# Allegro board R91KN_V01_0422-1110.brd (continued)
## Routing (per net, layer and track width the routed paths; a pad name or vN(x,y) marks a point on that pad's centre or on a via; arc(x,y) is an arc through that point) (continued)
ODTA1: length 49.4
  TOP w0.097: v3(128.95,68.44) 128.8,68.44 128.68,68.56 128.68,68.99 128.5,69.17 128.5,70.52 128.45,70.57 128.45,71.37 128.57,71.49 128.76,71.49 128.85,71.58 128.85,71.7 128.76,71.79 128.12,71.79 128.03,71.88 128.03,72 128.12,72.09 129.91,72.09 130,72.18 130,72.76 130.09,72.84 130.21,72.84 130.3,72.76 130.3,72.18 130.39,72.09 130.51,72.09 130.6,72.18 130.6,72.76 130.69,72.84 130.81,72.84 130.9,72.76 130.9,72.18 130.99,72.09 131.63,72.09 132.12,72.58 132.56,72.58
  BOTTOM w0.097: v3(128.95,68.44) 129.23,68.16 129.23,65.51 129.38,65.36 129.38,62.95 130.51,61.81 131.72,61.81 R228.2 ; R230.2 141,61.3 141,69.4 140.91,69.49 140.58,69.49 140.49,69.58 140.49,69.7 140.58,69.79 140.91,69.79 141,69.88 141,70 140.91,70.09 140.21,70.09 140.12,70.18 140.12,70.3 140.21,70.39 140.91,70.39 141,70.48 141,70.6 140.91,70.69 140.1,70.69 140.01,70.78 140.01,70.9 140.1,70.99 140.91,70.99 141,71.08 v4(141,71.61) 141,72.05 140.88,72.17 139.09,72.17 138.97,72.3 U402.K1
  BOTTOM w0.1: R230.2 140.48,60.81 139.76,60.09 R227.1 139.54,59.89 139.13,59.89 138.41,59.16 135.94,59.16 135.81,59.29 134.68,59.29 134.45,59.52 134.45,59.53 134.14,59.84 134.14,60.07 133.26,60.95 132.64,60.95 R228.2
ODTA1_R: length 42.7
  TOP w0.1: U1.K16 v1(95.9,59.05)
  BOTTOM w0.1: v1(95.9,59.05) 96.09,59.05 96.63,59.6 96.74,59.6 97.81,60.67 98.14,60.67 98.46,60.35 98.61,60.2 99.67,60.2 99.68,60.2 99.73,60.19 100.69,59.23 101.06,59.23 101.24,59.41 101.24,59.63 101.47,59.86 101.75,59.86 101.76,59.84 101.81,59.84 102.05,59.6 102.05,59.33 102.14,59.23 102.27,59.23 102.72,58.77 106.02,58.77 106.7,58.09 130.47,58.09 130.62,57.94 131.9,57.94 132.84,58.88 133.25,58.88 133.53,59.15 133.53,60.01 R228.1
PCIE_CALRN: length 2.3
  TOP w0.25: U1.AA22 86.98,54.6 87.61,53.97 v1(87.77,53.97)
  BOTTOM w0.3: v1(87.77,53.97) 87.54,53.97 87.13,53.55 R8.2
PCIE_CALRP: length 1.4
  TOP w0.3: v1(87.27,55.04) 87.29,55.04 87.73,54.6 U1.Y22
  BOTTOM w0.3: R9.1 86.85,55.59 87.27,55.17 v1(87.27,55.04)
PCIE_REFCLKN: length 56.1
  TOP w0.1: U1.AK32 80.12,48.2 79.98,48.06 79.98,47.81 80.21,47.58 80.21,47.23 79.95,46.98 79.85,46.98 79.7,46.82 v1(79.7,46.56)
  BOTTOM w0.125: v1(79.7,46.56) 79.78,46.64 79.78,46.79 79.65,46.91 79.39,46.91 79.15,46.67 79.15,40.27 74.95,36.08 74.95,22.8 66.35,14.2 63.27,14.2 60.3,11.23 60.3,6.1 60.65,5.75 MPCIE1.A14
PCIE_REFCLKP: length 56
  TOP w0.1: v1(79.81,47.42) 79.74,47.49 79.74,48.31 80.07,48.64 80.07,48.92 U1.AK30
  BOTTOM w0.125: v1(79.81,47.42) 79.6,47.21 79.27,47.21 78.93,46.88 78.85,46.79 78.85,40.4 74.65,36.2 74.65,22.92 66.23,14.5 63.15,14.5 60,11.35 60,6.1 59.65,5.75 MPCIE1.A13
PCIE_TX0N: length 47.5
  TOP w0.1: v1(81.05,46.67) 81.05,46.76 81.21,46.91 81.22,46.91 81.45,47.15 81.45,47.16 81.45,47.57 81.48,47.6 81.48,48.43 81.65,48.6 U1.AG31
  BOTTOM w0.125: C4.1 63.3,11.54 63.3,12.12 64.08,12.9 66.77,12.9 76.15,22.28 76.15,35.6 80.5,39.95 80.5,46.8 80.59,46.9 80.95,46.9 81.05,46.8 v1(81.05,46.67)
PCIE_TX0P: length 47.5
  TOP w0.1: v1(81.05,47.31) 81.05,47.45 81.28,47.68 81.28,48.67 U1.AH30
  BOTTOM w0.125: C3.1 63,11.54 63,12.24 63.96,13.2 66.65,13.2 75.85,22.4 75.85,35.72 80.19,40.07 80.19,46.92 80.47,47.2 80.94,47.2 v1(81.05,47.31)
PCIE_TX1N: length 45.7
  TOP w0.125: v1(82.17,50.23) 82.17,50.18 U1.AF28
  BOTTOM w0.125: C6.1 68.3,11.54 68.3,11.95 77.35,21 77.35,34.8 81.88,39.33 81.88,48.41 82.15,48.68 82.15,49.74 81.99,49.91 81.99,50.05 v1(82.17,50.23)
PCIE_TX1P: length 45.7
  TOP w0.125: v1(81.43,50.04) 81.75,49.72 U1.AG29
  BOTTOM w0.125: v1(81.43,50.04) 81.85,49.62 81.85,48.8 81.58,48.54 81.58,39.46 77.05,34.92 77.05,21.12 68,12.07 68,11.54 C5.1
PCIE_TX2N: length 45.2
  TOP w0.125: U1.AF26 82.56,51.4 82.95,51.01 v1(82.95,51)
  BOTTOM w0.125: C9.1 72.3,11.54 72.3,12.35 78.75,18.8 78.75,34.48 83.05,38.78 83.05,48.05 82.9,48.21 82.9,50.52 82.73,50.69 82.73,50.83 82.9,51 v1(82.95,51)
PCIE_TX2P: length 45.2
  TOP w0.125: v1(82.15,51) 82.15,50.98 82.53,50.6 U1.AF27
  BOTTOM w0.125: v1(82.15,51) 82.43,50.72 82.43,50.57 82.6,50.39 82.6,48.08 82.75,47.93 82.75,38.9 78.45,34.6 78.45,18.92 72,12.47 72,11.54 C7.1
PCIE_TX3N: length 44.1
  TOP w0.125: U1.AD26 84.15,51.38 v1(84.56,50.98)
  BOTTOM w0.125: C11.1 76.3,11.54 76.3,12.23 80.05,15.98 80.05,33.7 83.93,37.58 83.93,47.19 83.74,47.38 83.74,49.43 84.07,49.76 84.07,50.49 v1(84.56,50.98)
PCIE_TX3P: length 44.1
  TOP w0.125: U1.AD27 84.15,50.8 83.95,51 v1(83.7,51)
  BOTTOM w0.125: v1(83.7,51) 83.77,50.93 83.77,49.89 83.44,49.55 83.44,47.25 83.63,47.06 83.63,37.7 79.75,33.82 79.75,16.1 76,12.35 76,11.54 C10.1
PCIE_TX4N: length 43.7
  TOP w0.102: U1.AB25 85.83,52.2 85.45,52.57 v1(85.45,52.58)
  BOTTOM w0.125: C13.1 82.3,11.54 82.3,33.83 84.86,36.39 84.86,47.89 84.61,48.14 84.61,49.48 85.01,49.88 85.01,50.4 85.27,50.66 85.27,52.4 v1(85.45,52.58)
PCIE_TX4P: length 43.7
  TOP w0.102: v1(84.58,52.58) 84.61,52.58 84.95,52.23 U1.AC25
  BOTTOM w0.125: v1(84.58,52.58) 84.97,52.18 84.97,50.78 84.71,50.52 84.71,50.01 84.31,49.6 84.31,48.02 84.56,47.76 84.56,36.51 82,33.95 82,11.54 C12.1
PCIE_TX5N: length 44.2
  TOP w0.102: U1.Y24 87.02,53.13 86.89,53.13 86.65,52.9 v1(86.65,52.62)
  BOTTOM w0.1: v1(86.65,52.62) 86.65,52.77 86.51,52.91 86.23,52.91 86.08,52.76 86.08,50.67 85.67,50.27 85.67,48.36 85.34,48.03 85.34,47.27 85.55,47.07 85.55,46.63 85.6,46.58 85.6,46.56
  BOTTOM w0.125: C16.1 86.65,11.64 86.3,11.99 86.3,20.35 85.9,20.75 85.9,44.71 85.73,44.88 85.6,45.01 85.6,46.56
PCIE_TX5P: length 44.2
  TOP w0.102: U1.Y23 87.15,53.8 86.7,53.35 v1(86.45,53.35)
  BOTTOM w0.1: 85.3,46.56 85.3,46.58 85.35,46.63 85.35,46.98 85.14,47.19 85.14,48.11 85.47,48.44 85.47,50.35 85.88,50.76 85.88,52.84 86.15,53.11 86.21,53.11 v1(86.45,53.35)
  BOTTOM w0.125: 85.3,46.56 85.3,44.88 85.6,44.58 85.6,20.63 86,20.23 86,11.99 85.65,11.64 C15.1
PCIE_TX6N: length 44.1
  TOP w0.125: v1(86.55,51.95) 86,51.4 U1.AB26
  BOTTOM w0.1: v1(86.55,51.95) 86.81,51.69 86.95,51.69 87.23,51.4 87.23,49.74 86.36,48.87 86.36,47.12 86.41,47.07 86.41,47.04
  BOTTOM w0.125: C18.1 90.3,11.54 90.3,28.34 86.83,31.81 86.83,45.46 86.41,45.89 86.41,47.04
PCIE_TX6P: length 44.1
  TOP w0.125: v1(86.5,51.13) 85.97,50.6 U1.AB27
  BOTTOM w0.1: v1(86.5,51.13) 86.5,51.32 86.66,51.49 86.86,51.49 87.03,51.31 87.03,49.83 86.16,48.95 86.16,47.12 86.11,47.07 86.11,47.04
  BOTTOM w0.125: C17.1 90,11.54 90,28.22 86.53,31.68 86.53,45.34 86.11,45.76 86.11,47.04
PCIE_TX7N: length 44.8
  TOP w0.125: v1(87.74,50.99) 87.56,50.99 U1.Y26
  BOTTOM w0.1: v1(87.74,50.99) 88.03,50.7 88.17,50.7 88.55,50.31 88.55,49.82 86.94,48.21 86.94,47.33 87.11,47.16 87.11,46.91 87.16,46.86 87.16,46.84
  BOTTOM w0.125: C22.1 94.3,11.54 94.3,27.87 87.77,34.41 87.77,45.84 87.16,46.45 87.16,46.84
PCIE_TX7P: length 44.8
  TOP w0.125: v1(87.85,50.05) 87.85,50.35 87.6,50.6 U1.Y27
  BOTTOM w0.1: 86.86,46.84 86.86,46.86 86.91,46.91 86.91,47.08 86.74,47.24 86.74,48.29 88.35,49.9 88.35,50.23 88.09,50.5 87.93,50.5 87.85,50.41 v1(87.85,50.05)
  BOTTOM w0.125: 86.86,46.84 86.86,46.33 87.47,45.72 87.47,34.28 94,27.75 94,11.54 C19.1
PCIE_TX8N: length 48.8
  TOP w0.102: v1(87.8,53.33) 87.81,53.33 88.28,53.8 U1.W23
  BOTTOM w0.1: v1(87.8,53.33) 88.07,53.06 88.25,53.06 88.52,52.79 88.52,51.05 89.07,50.5 89.07,49.4 88.01,48.34 88.01,47.22 88.06,47.17 88.06,47.14
  BOTTOM w0.125: 88.06,47.14 88.06,46.81 88.7,46.18 88.7,36.93 99.3,26.33 99.3,11.54 C24.1
PCIE_TX8P: length 48.8
  TOP w0.102: U1.W24 88.04,53 87.8,52.76 v1(87.8,52.48)
  BOTTOM w0.1: v1(87.8,52.48) 87.8,52.65 88.01,52.86 88.17,52.86 88.32,52.71 88.32,50.97 88.87,50.42 88.87,49.48 87.81,48.42 87.81,47.22 87.76,47.17 87.76,47.14
  BOTTOM w0.125: C23.1 99,11.54 99,26.2 88.4,36.8 88.4,46.05 87.76,46.69 87.76,47.14
PCIE_TX9N: length 48.7
  TOP w0.102: U1.U26 89.37,51.58 89.37,51.6 88.97,51.99 v1(88.97,52)
  BOTTOM w0.1: 88.94,47.05 88.92,47.07 88.85,47.07 88.62,47.3 88.62,48.01 89.66,49.04 89.66,51.49 89.39,51.76 89.21,51.76 v1(88.97,52)
  BOTTOM w0.125: 88.94,47.05 89.66,46.33 89.66,38.64 103.3,25 103.3,11.54 C26.1
PCIE_TX9P: length 48.8
  TOP w0.1: U1.V27 88.97,50.62
  TOP w0.102: v1(88.97,51.32) 89.09,51.32 89.31,51.1 89.31,50.73 89.2,50.62 88.97,50.62
  BOTTOM w0.1: 88.73,46.84 88.71,46.86 88.71,46.93 88.42,47.22 88.42,48.09 89.46,49.13 89.46,51.41 89.31,51.56 89.13,51.56 88.97,51.4 v1(88.97,51.32)
  BOTTOM w0.125: 88.73,46.84 89.36,46.21 89.36,38.51 103,24.87 103,11.54 C25.1
PCIE_TX10N: length 50.8
  TOP w0.125: v1(90.03,53.45) 89.73,53.45 89.55,53.63 U1.U23
  BOTTOM w0.1: v1(90.03,53.45) 89.87,53.45 89.61,53.18 89.61,52.46 90.19,51.87 90.19,48.64 90.04,48.49 90.04,47.88 90.09,47.83 90.09,47.8
  BOTTOM w0.125: 90.09,47.8 90.09,47.07 90.68,46.48 90.68,40 107.3,23.38 107.3,11.54 C29.1
PCIE_TX10P: length 50.8
  TOP w0.125: U1.U24 89.32,53 v1(88.91,53.41)
  BOTTOM w0.1: v1(88.91,53.41) 88.93,53.41 89.41,52.93 89.41,52.37 89.99,51.79 89.99,48.72 89.84,48.57 89.84,47.88 89.79,47.83 89.79,47.8
  BOTTOM w0.125: C28.1 107,11.54 107,23.25 90.38,39.87 90.38,46.36 89.79,46.95 89.79,47.8
PCIE_TX11N: length 50.5
  TOP w0.102: U1.T27 90.75,50.8 90.76,50.8 91.11,51.15 v1(91.28,51.15)
  BOTTOM w0.1: v1(91.28,51.15) 91.28,51.27 91.11,51.44 90.88,51.44 90.73,51.28 90.73,48.55 91.57,47.7 91.57,47.4 91.62,47.35 91.62,47.32
  BOTTOM w0.125: 91.62,47.32 91.62,41.12 111.3,21.44 111.3,11.54 C31.1
PCIE_TX11P: length 50.5
  TOP w0.102: U1.T26 90.87,51.4 91.28,51.8 v1(91.28,51.83)
  BOTTOM w0.1: 91.32,47.32 91.32,47.35 91.37,47.4 91.37,47.62 90.53,48.46 90.53,51.36 90.8,51.63 91.09,51.63 v1(91.28,51.83)
  BOTTOM w0.125: 91.32,47.32 91.32,40.99 111,21.32 111,11.54 C30.1
PCIE_TX12N: length 53.4
  TOP w0.102: v1(91.32,53.36) 91.32,53.37 90.89,53.8 U1.T23
  BOTTOM w0.1: 92.53,46.46 92.53,46.48 92.47,46.53 92.47,46.98 92.76,47.27 92.76,47.78 91.9,48.64 91.9,52.07 92,52.17 92,52.84 91.7,53.13 91.55,53.13 v1(91.32,53.36)
  BOTTOM w0.125: C36.1 115.3,11.54 115.3,19.32 92.53,42.09 92.53,46.46
PCIE_TX12P: length 53.5
  TOP w0.102: U1.T24 90.81,53.06 91.01,53.06 91.3,52.78 91.3,52.65 v1(91.25,52.6)
  BOTTOM w0.1: v1(91.25,52.6) 91.25,52.82 91.36,52.93 91.62,52.93 91.8,52.76 91.8,52.25 91.7,52.15 91.7,48.56 92.56,47.7 92.56,47.35 92.28,47.07 92.28,46.53 92.22,46.48 92.22,46.46
  BOTTOM w0.125: C32.1 115,11.54 115,19.2 92.22,41.97 92.22,46.46
PCIE_TX13N: length 53.2
  TOP w0.102: U1.P26 92.05,51.4 92.42,51.77 v1(92.45,51.77)
  BOTTOM w0.1: v1(92.45,51.77) 92.7,51.52 92.88,51.52 93.09,51.31 93.09,50.72 92.38,50.01 92.38,48.95 93.29,48.04 93.29,47.25 93.59,46.96 93.59,46.53 93.64,46.48 93.64,46.46
  BOTTOM w0.125: 93.64,46.46 93.64,42.55 119.3,16.89 119.3,11.54 C38.1
PCIE_TX13P: length 53.2
  TOP w0.102: U1.P27 92.09,50.6 91.98,50.71 91.98,50.9 92.15,51.08 v1(92.45,51.08)
  BOTTOM w0.1: v1(92.45,51.08) 92.7,51.33 92.79,51.33 92.89,51.23 92.89,50.8 92.18,50.09 92.18,48.87 93.09,47.96 93.09,47.17 93.39,46.87 93.39,46.53 93.34,46.48 93.34,46.46
  BOTTOM w0.125: 93.34,46.46 93.34,42.43 119,16.76 119,11.54 C37.1
PCIE_TX14N: length 56.3
  TOP w0.102: v1(92.55,53.88) 92.47,53.8 U1.P23
  BOTTOM w0.1: 94.46,47.07 94.46,47.09 94.41,47.14 94.41,47.83 93.6,48.64 93.6,51.44 93.27,51.77 93.27,53.37 93.01,53.62 92.8,53.62 v1(92.55,53.88)
  BOTTOM w0.125: C40.1 123.3,11.54 123.3,14.52 94.46,43.36 94.46,47.07
PCIE_TX14P: length 56.3
  TOP w0.102: v1(92.55,53.17) 92.34,53.38 92.11,53.38 91.95,53.22 U1.P24
  BOTTOM w0.1: v1(92.55,53.17) 92.8,53.42 92.93,53.42 93.07,53.29 93.07,51.69 93.4,51.36 93.4,48.56 94.21,47.75 94.21,47.14 94.16,47.09 94.16,47.07
  BOTTOM w0.125: C39.1 123,11.54 123,14.4 94.16,43.23 94.16,47.07
PCIE_TX15N: length 57.4
  TOP w0.102: v1(93.67,52.5) 93.53,52.35 93.53,51.96 93.15,51.59 U1.N26
  BOTTOM w0.1: 95.13,47.22 95.13,47.24 95.08,47.29 95.08,48.13 94.21,49 94.21,51.1 94.67,51.56 94.67,52.04 94.35,52.36 93.82,52.36 v1(93.67,52.5)
  BOTTOM w0.125: C42.1 127.3,11.54 127.3,12.27 95.48,44.09 95.48,45.55 95.13,45.9 95.13,47.22
PCIE_TX15P: length 57.4
  TOP w0.102: U1.M27 93.62,50.6 93.56,50.66 93.56,51.64 93.71,51.8 v1(93.9,51.8)
  BOTTOM w0.1: 94.83,47.22 94.83,47.24 94.88,47.29 94.88,48.05 94.01,48.92 94.01,51.18 94.47,51.64 94.47,51.96 94.27,52.16 94.01,52.16 93.9,52.06 v1(93.9,51.8)
  BOTTOM w0.125: 94.83,47.22 94.83,45.78 95.18,45.43 95.18,43.97 127,12.15 127,11.54 C41.1
PERN0: length 7
  BOTTOM w0.125: C4.2 63.3,9.86 63.3,6.1 63.65,5.75 MPCIE1.A17
PERN1: length 7
  BOTTOM w0.125: C6.2 68.3,9.86 68.3,6.1 68.65,5.75 MPCIE1.A22
PERN2: length 7
  BOTTOM w0.125: MPCIE1.A26 72.65,5.75 72.3,6.1 72.3,9.86 C9.2
PERN3: length 7
  BOTTOM w0.125: C11.2 76.3,9.86 76.3,6.1 76.65,5.75 MPCIE1.A30
PERN4: length 7
  BOTTOM w0.125: MPCIE1.A36 82.65,5.75 82.3,6.1 82.3,9.86 C13.2
PERN5: length 7
  BOTTOM w0.125: MPCIE1.A40 86.65,5.75 86.3,6.1 86.3,9.86 C16.2
PERN6: length 7
  BOTTOM w0.125: C18.2 90.3,9.86 90.3,6.1 90.65,5.75 MPCIE1.A44
PERN7: length 7
  BOTTOM w0.125: C22.2 94.3,9.86 94.3,6.1 94.65,5.75 MPCIE1.A48
PERN8: length 7
  BOTTOM w0.125: MPCIE1.A53 99.65,5.75 99.3,6.1 99.3,9.86 C24.2
PERN9: length 7
  BOTTOM w0.125: C26.2 103.3,9.86 103.3,6.1 103.65,5.75 MPCIE1.A57
PERN10: length 7
  BOTTOM w0.125: MPCIE1.A61 107.65,5.75 107.3,6.1 107.3,9.86 C29.2
PERN11: length 7
  BOTTOM w0.125: C31.2 111.3,9.86 111.3,6.1 111.65,5.75 MPCIE1.A65
PERN12: length 7
  BOTTOM w0.125: C36.2 115.3,9.86 115.3,6.1 115.65,5.75 MPCIE1.A69
PERN13: length 7
  BOTTOM w0.125: C38.2 119.3,9.86 119.3,6.1 119.65,5.75 MPCIE1.A73
PERN14: length 7
  BOTTOM w0.125: C40.2 123.3,9.86 123.3,6.1 123.65,5.75 MPCIE1.A77
PERN15: length 7
  BOTTOM w0.125: C42.2 127.3,9.86 127.3,6.1 127.65,5.75 MPCIE1.A81
PERP0: length 7
  BOTTOM w0.125: MPCIE1.A16 62.65,5.75 63,6.1 63,9.86 C3.2
PERP1: length 7
  BOTTOM w0.125: MPCIE1.A21 67.65,5.75 68,6.1 68,9.86 C5.2
PERP2: length 7
  BOTTOM w0.125: MPCIE1.A25 71.65,5.75 72,6.1 72,9.86 C7.2
PERP3: length 7
  BOTTOM w0.125: MPCIE1.A29 75.65,5.75 76,6.1 76,9.86 C10.2
PERP4: length 7
  BOTTOM w0.125: C12.2 82,9.86 82,6.1 81.65,5.75 MPCIE1.A35
PERP5: length 7
  BOTTOM w0.125: C15.2 86,9.86 86,6.1 85.65,5.75 MPCIE1.A39
PERP6: length 7
  BOTTOM w0.125: MPCIE1.A43 89.65,5.75 90,6.1 90,9.86 C17.2
PERP7: length 7
  BOTTOM w0.125: MPCIE1.A47 93.65,5.75 94,6.1 94,9.86 C19.2
PERP8: length 7
  BOTTOM w0.125: C23.2 99,9.86 99,6.1 98.65,5.75 MPCIE1.A52
PERP9: length 7
  BOTTOM w0.125: C25.2 103,9.86 103,6.1 102.65,5.75 MPCIE1.A56
PERP10: length 7
  BOTTOM w0.125: MPCIE1.A60 106.65,5.75 107,6.1 107,9.86 C28.2
PERP11: length 7
  BOTTOM w0.125: C30.2 111,9.86 111,6.1 110.65,5.75 MPCIE1.A64
PERP12: length 7
  BOTTOM w0.125: MPCIE1.A68 114.65,5.75 115,6.1 115,9.86 C32.2
PERP13: length 7
  BOTTOM w0.125: MPCIE1.A72 118.65,5.75 119,6.1 119,9.86 C37.2
PERP14: length 7
  BOTTOM w0.125: C39.2 123,9.86 123,6.1 122.65,5.75 MPCIE1.A76
PERP15: length 7
  BOTTOM w0.125: C41.2 127,9.86 127,6.1 126.65,5.75 MPCIE1.A80
PERST#: length 12
  TOP w0.1: U4.2 57.95,13.4 57.74,13.19 R61.1 55.9,9.86 v3(55.42,9.86)
  BOTTOM w0.1: v3(55.42,9.86) 55.42,3.73 MPCIE1.A11
PERST#_BUF: length 163.9
  TOP w0.1: D4400.2 107.05,103.6 102.72,99.26 99.9,99.26 98.88,98.25 98.88,96.62 96.9,94.64 95.61,94.64 R4054.1 v3(93.9,95.3) ; v3(60.35,39.85) 59.16,38.66 59.16,31.78 58.47,31.09 58.47,24.88 59.59,23.76 59.59,17.04 56.7,14.15 U4.4 57,14.05 57.35,13.7 57.35,12.29 R61.2 ; U1.AL27 78.81,50.6 75.6,47.38 75.6,47.13 74.11,45.64 58.23,45.64 v3(58.09,45.5)
  BOTTOM w0.1: v3(93.9,95.3) 75.65,95.3 72.45,92.1 72.45,85.2 71.85,84.6 70.16,84.6 68.16,86.6 65.75,86.6 64.24,85.09 64.24,80.14 58.09,73.99 v3(58.09,45.5) 58.09,39.65 58.34,39.4 59.89,39.4 v3(60.35,39.85)
PERST#_CTFIN: length 3.1
  TOP w0.1: Q4013.1 96.03,96.54 R4061.2 R4054.2
PETN0_GFXRN0: length 55.8
  TOP w0.1: U1.AE31 83.35,48.67 83.22,48.79 83.11,48.79 82.98,48.66 82.98,48.53 83.16,48.35 83.16,47.23 82.75,46.81 82.75,46.74 82.73,46.72
  TOP w0.125: MPCIE1.B15 61.65,5.75 61.3,6.1 61.3,8.12 73.95,20.77 73.95,25.5 TP102.1 73.95,26.5 73.95,36.54 74.85,37.44 74.85,39.5 81.1,45.75 81.76,45.75 82.73,46.72
PETN1_GFXRN1: length 53.9
  TOP w0.1: U1.AD28 84.15,49.79 83.89,49.53 83.89,49.2 83.88,49.19 83.79,49.11 83.76,49.07 83.76,48.94 83.87,48.81 83.87,48.38 83.75,48.26 83.75,47.72 83.72,47.68 83.72,46.7 83.19,46.18 83.19,46.11 83.18,46.1
  TOP w0.125: MPCIE1.B20 66.65,5.75 66.3,6.1 66.3,8.47 75.45,17.62 75.45,36.29 76.35,37.19 76.35,39.27 83.18,46.1
PETN2_GFXRN2: length 52.3
  TOP w0.1: U1.AC31 84.95,48.66 84.85,48.76 84.73,48.76 84.63,48.66 84.63,48.46 84.84,48.25 84.84,47.38 84.42,46.96 84.42,46.71 84.47,46.66 84.47,46.63
  TOP w0.125: 84.47,46.63 84.47,46.17 77.55,39.25 77.55,36.53 76.95,35.93 76.95,26.5 TP104.1 76.95,25.5 76.95,16.18 70.3,9.53 70.3,6.1 70.65,5.75 MPCIE1.B24
PETN3_GFXRN3: length 51.7
  TOP w0.1: 85.38,46.79 85.38,46.82 85.33,46.87 85.33,48.24 85.47,48.38 85.47,48.82 85.42,48.87 85.42,48.87 85.41,48.88 85.41,49.12 85.52,49.23 85.52,49.57 U1.AB28
  TOP w0.125: 85.38,46.79 85.38,45.81 79.55,39.98 79.55,26.5 TP106.1 79.55,25.5 79.55,15.01 74.3,9.76 74.3,6.1 74.65,5.75 MPCIE1.B28
PETN4_GFXRN4: length 48.4
  TOP w0.1: 86.1,46.56 86.1,46.59 86.05,46.64 86.05,46.92 86.41,47.27 86.41,48.27 86.3,48.38 86.16,48.52 86.16,48.59 86.28,48.72 86.43,48.72 U1.AA31
  TOP w0.125: MPCIE1.B34 80.65,5.75 80.3,6.1 80.3,7.69 81.38,8.77 81.38,40.52 86.1,45.24 86.1,46.56
PETN5_GFXRN5: length 49.2
  TOP w0.1: U1.Y28 87.09,49.54 87.09,49.2 87,49.11 87,48.89 87.08,48.82 87.08,48.38 86.89,48.19 86.89,46.79 86.94,46.74 86.94,46.71
  TOP w0.125: MPCIE1.B38 84.65,5.75 84.3,6.1 84.3,20.67 TP108.1 84.3,21.57 84.3,23.45 83.13,24.62 83.13,41.13 86.94,44.93 86.94,46.71
PETN6_GFXRN6: length 48.9
  TOP w0.1: U1.W31 88.03,48.72 87.83,48.72 87.76,48.65 87.76,48.52 87.96,48.32 87.96,47.17 87.78,46.99 87.78,46.73 87.83,46.68 87.83,46.66
  TOP w0.125: 87.83,46.66 87.83,44.3 84.91,41.39 84.91,26.66 88.3,23.27 88.3,21.57 TP110.1 88.3,20.67 88.3,6.1 88.65,5.75 MPCIE1.B42
PETN7_GFXRN7: length 50
  TOP w0.1: U1.V28 88.69,49.54 88.69,49.2 88.63,49.14 88.63,48.85 88.69,48.8 88.69,48.39 88.55,48.25 88.55,47.42 88.73,47.24 88.73,46.79 88.78,46.74 88.78,46.71
  TOP w0.125: 86.64,41.74 88.37,43.47 88.78,43.87 88.78,46.71
  TOP w0.127: MPCIE1.B46 92.65,5.75 92.3,6.1 92.3,22.41 86.64,28.07 86.64,41.74
PETN8_GFXRN8: length 50.8
  TOP w0.1: U1.U31 89.59,48.76 89.49,48.76 89.39,48.66 89.39,48.49 89.64,48.24 89.64,47.35 89.55,47.26 89.55,46.91 89.59,46.86 89.59,46.84
  TOP w0.125: MPCIE1.B51 97.65,5.75 97.3,6.1 97.3,22.85 TP112.1 97.3,23.75 97.3,25.22 88.06,34.46 88.06,41.84 89.59,43.37 89.59,46.84
PETN9_GFXRN9: length 52.4
  TOP w0.1: U1.T28 90.55,49.79 90.34,49.58 90.34,49.24 90.22,49.12 90.22,48.88 90.3,48.81 90.3,48.39 90.29,48.38 90.29,48.38 90.2,48.29 90.2,47.4 90.36,47.23 90.36,46.76 90.41,46.71 90.41,46.69
  TOP w0.125: 90.41,46.69 90.41,42.84 89.99,42.42
  TOP w0.127: 89.99,42.42 89.48,41.91 89.48,36.24 101.3,24.42 101.3,23.75 TP114.1 101.3,22.85 101.3,6.1 101.65,5.75 MPCIE1.B55
PETN10_GFXRN10: length 51.8
  TOP w0.1: U1.R31 91.21,48.74 91.1,48.74 90.99,48.63 90.99,48.49 91.16,48.32 91.16,47.89 91.31,47.74 91.31,47.27 91.13,47.09 91.13,46.99 91.18,46.94 91.18,46.91
  TOP w0.127: 91.18,46.91 91.18,36.87 105.3,22.75 105.3,6.1 105.65,5.75 MPCIE1.B59
PETN11_GFXRN11: length 54.3
  TOP w0.1: U1.P28 91.9,49.55 91.9,49.21 91.83,49.13 91.83,48.86 91.88,48.8 91.88,48.41 91.88,48.4 91.87,48.39 91.87,48.39 91.73,48.25 91.73,47.32 91.93,47.11 91.93,46.76 91.98,46.71 91.98,46.69
  TOP w0.125: 99.78,30.83 92.79,37.82 92.79,39.46 91.98,40.27 91.98,46.69
  TOP w0.127: 99.78,30.83 99.78,30.83 109.3,21.31 109.3,20.25 TP116.1 109.3,19.35 109.3,6.1 109.65,5.75 MPCIE1.B63
PETN12_GFXRN12: length 54.8
  TOP w0.1: U1.N31 92.83,48.72 92.63,48.72 92.56,48.64 92.56,48.53 92.78,48.31 92.78,47.21 92.65,47.08 92.65,46.88 92.7,46.83 92.7,46.8
  TOP w0.125: 92.7,46.8 92.7,41.65 94.49,39.86 94.49,37.85 101.84,30.49
  TOP w0.127: MPCIE1.B67 113.65,5.75 113.3,6.1 113.3,14.95 TP118.1 113.3,15.85 113.3,19.04 101.84,30.49
PETN13_GFXRN13: length 56.6
  TOP w0.1: 93.45,47.01 93.4,47.06 93.4,47.36 93.29,47.47 93.29,48.17 93.38,48.27 93.5,48.41 93.5,48.79 93.42,48.87 93.42,49.11 93.49,49.18 93.49,49.53 93.75,49.78 U1.M28
  TOP w0.125: 93.45,47.01 93.45,42.5 95.67,40.28 95.67,38.22 102.18,31.71 102.18,31.71 102.25,31.64 102.25,31.64 102.27,31.62
  TOP w0.127: 102.27,31.62 109.74,24.15 117.3,16.59 117.3,6.1 117.65,5.75 MPCIE1.B71
PETN14_GFXRN14: length 57.5
  TOP w0.1: U1.L31 94.41,48.74 94.26,48.74 94.16,48.64 94.16,48.53 94.4,48.29 94.4,47.23 94.24,47.07 94.24,46.84 94.29,46.79 94.29,46.76
  TOP w0.125: 102.85,32.8 102.83,32.82 102.83,32.82 102.76,32.89 102.76,32.89 97.4,38.25 97.4,40.28 94.29,43.39 94.29,46.76
  TOP w0.127: MPCIE1.B75 121.65,5.75 121.3,6.1 121.3,12.65 TP120.1 121.3,13.55 121.3,14.35 102.85,32.8
PETN15_GFXRN15: length 59.2
  TOP w0.1: U1.K30 95.22,49.13 95.06,49.13 94.98,49.06 94.98,48.91 95.07,48.83 95.07,48.36 94.97,48.26 94.97,46.64 95.02,46.59 95.02,46.56
  TOP w0.125: TP122.1 125.3,11.55 125.3,12.27 98.65,38.92 98.65,40.92 95.02,44.56 95.02,46.56
  TOP w0.127: TP122.1 125.3,10.65 125.3,6.1 125.65,5.75 MPCIE1.B79
PETP0_GFXRP0: length 55.8
  TOP w0.1: 82.52,46.93 82.53,46.95 82.61,46.95 82.96,47.31 82.96,48.26 82.78,48.45 82.78,48.77 U1.AF30
  TOP w0.125: 82.52,46.93 81.63,46.05 80.97,46.05 74.55,39.62 74.55,37.57 73.65,36.67 73.65,26.5 TP101.1 73.65,25.5 73.65,20.89 61,8.24 61,6.1 60.65,5.75 MPCIE1.B14
PETP1_GFXRP1: length 54
  TOP w0.1: U1.AE29 83.35,49.43 83.45,49.53 83.6,49.53 83.69,49.44 83.69,49.28 83.64,49.24 83.56,49.14 83.56,48.87 83.67,48.74 83.67,48.46 83.55,48.34 83.55,47.8 83.52,47.76 83.52,46.79 83.05,46.33 82.98,46.33 82.97,46.31
  TOP w0.125: 82.97,46.31 76.05,39.39 76.05,37.31 75.15,36.41 75.15,17.75 66,8.6 66,6.1 65.65,5.75 MPCIE1.B19
PETP2_GFXRP2: length 52.3
  TOP w0.1: 84.17,46.63 84.17,46.66 84.22,46.71 84.22,47.04 84.64,47.46 84.64,48.17 84.43,48.38 84.43,48.72 U1.AD30
  TOP w0.125: MPCIE1.B23 69.65,5.75 70,6.1 70,9.65 76.65,16.3 76.65,25.5 TP103.1 76.65,26.5 76.65,36.05 77.25,36.65 77.25,39.37 84.17,46.3 84.17,46.63
PETP3_GFXRP3: length 51.7
  TOP w0.1: 85.08,46.79 85.08,46.82 85.13,46.87 85.13,48.32 85.27,48.47 85.27,48.73 85.22,48.78 85.21,48.8 85.21,48.88 85.21,49.2 85.32,49.31 85.32,49.46 85.25,49.53 85.08,49.53 U1.AC29
  TOP w0.125: 85.08,46.79 85.08,45.94 79.25,40.11 79.25,26.5 TP105.1 79.25,25.5 79.25,15.13 74,9.88 74,6.1 73.65,5.75 MPCIE1.B27
PETP4_GFXRP4: length 48.4
  TOP w0.1: U1.AB30 85.96,48.79 85.96,48.43 86.11,48.28 86.21,48.18 86.21,47.36 85.85,47 85.85,46.64 85.8,46.59 85.8,46.56
  TOP w0.125: MPCIE1.B33 79.65,5.75 80,6.1 80,7.81 81.08,8.89 81.08,40.64 85.8,45.37 85.8,46.56
PETP5_GFXRP5: length 49.1
  TOP w0.1: 86.64,46.71 86.64,46.74 86.69,46.79 86.69,48.28 86.88,48.47 86.88,48.73 86.8,48.81 86.8,49.19 86.89,49.28 86.89,49.44 86.8,49.53 86.65,49.53 86.55,49.43 U1.AA29
  TOP w0.125: MPCIE1.B37 83.65,5.75 84,6.1 84,20.67 TP107.1 84,21.57 84,23.32 82.83,24.49 82.83,41.25 86.64,45.06 86.64,46.71
PETP6_GFXRP6: length 48.9
  TOP w0.1: 87.53,46.66 87.53,46.68 87.58,46.73 87.58,47.07 87.76,47.25 87.76,48.24 87.56,48.44 87.56,48.79 U1.Y30
  TOP w0.125: MPCIE1.B41 87.65,5.75 88,6.1 88,20.67 TP109.1 88,21.57 88,23.15 84.61,26.54 84.61,41.51 87.53,44.43 87.53,46.66
PETP7_GFXRP7: length 49.9
  TOP w0.1: U1.W29 88.15,49.43 88.25,49.53 88.4,49.53 88.49,49.44 88.49,49.28 88.43,49.23 88.43,48.77 88.49,48.72 88.49,48.47 88.35,48.33 88.35,47.33 88.53,47.16 88.53,46.79 88.48,46.74 88.48,46.71
  TOP w0.125: 88.48,46.71 88.48,44 87.7,43.22 86.52,42.04 86.51,42.04 86.34,41.86 86.34,41.77 86.34,41.74
  TOP w0.127: MPCIE1.B45 91.65,5.75 92,6.1 92,22.28 86.34,27.94 86.34,41.74
PETP8_GFXRP8: length 50.7
  TOP w0.1: U1.V30 89.17,48.78 89.17,48.43 89.27,48.33 89.44,48.16 89.44,47.43 89.34,47.34 89.34,46.91 89.3,46.86 89.3,46.84
  TOP w0.125: MPCIE1.B50 96.65,5.75 97,6.1 97,22.85 TP111.1 97,23.75 97,25.1 87.76,34.34 87.76,41.96 89.3,43.5 89.3,46.84
PETP9_GFXRP9: length 52.4
  TOP w0.1: 90.11,46.69 90.11,46.71 90.16,46.76 90.16,47.15 90,47.31 90,48.37 90.1,48.47 90.1,48.72 90.02,48.8 90.02,49.2 90.14,49.32 90.14,49.43 90.06,49.51 89.86,49.51 U1.U29
  TOP w0.125: 89.78,42.63 89.8,42.65 89.8,42.65 89.87,42.72 89.87,42.72 90.11,42.96 90.11,46.69
  TOP w0.127: 89.78,42.63 89.18,42.04 89.18,36.12 101,24.3 101,23.75 TP113.1 101,22.85 101,6.1 100.65,5.75 MPCIE1.B54
PETP10_GFXRP10: length 51.8
  TOP w0.1: U1.T30 90.79,48.76 90.79,48.41 90.96,48.24 90.96,47.81 91.11,47.65 91.11,47.35 90.93,47.17 90.93,46.99 90.88,46.94 90.88,46.91
  TOP w0.127: MPCIE1.B58 104.65,5.75 105,6.1 105,22.62 90.88,36.74 90.88,46.91
PETP11_GFXRP11: length 54.3
  TOP w0.1: 91.68,46.69 91.68,46.71 91.73,46.76 91.73,47.03 91.53,47.23 91.53,48.33 91.66,48.47 91.66,48.47 91.68,48.49 91.68,48.72 91.63,48.78 91.63,49.22 91.69,49.28 91.69,49.45 91.59,49.55 91.45,49.55 91.35,49.45 U1.R29
  TOP w0.125: 91.68,46.69 91.68,40.14 92.49,39.34 92.49,37.7 99.48,30.71 99.48,30.7 99.65,30.53 99.66,30.53 99.67,30.52
  TOP w0.127: 99.67,30.52 109,21.18 109,20.25 TP115.1 109,19.35 109,6.1 108.65,5.75 MPCIE1.B62
PETP12_GFXRP12: length 54.8
  TOP w0.1: 92.4,46.8 92.4,46.83 92.45,46.88 92.45,47.16 92.58,47.29 92.58,48.23 92.36,48.45 92.36,48.79 U1.P30
  TOP w0.125: 101.53,30.38 94.19,37.73 94.19,39.74 92.4,41.53 92.4,46.8
  TOP w0.127: MPCIE1.B66 112.65,5.75 113,6.1 113,14.95 TP117.1 113,15.85 113,18.91 101.53,30.38 101.53,30.38
PETP13_GFXRP13: length 56.7
  TOP w0.1: 93.15,47 93.15,47.02 93.2,47.07 93.2,47.28 93.09,47.39 93.09,48.25 93.23,48.4 93.3,48.49 93.3,48.7 93.22,48.79 93.22,49.19 93.29,49.26 93.29,49.46 93.19,49.56 93.05,49.56 92.95,49.46 U1.N29
  TOP w0.125: 93.15,47 93.15,42.38 95.37,40.16 95.37,38.09 102.05,31.41
  TOP w0.127: MPCIE1.B70 116.65,5.75 117,6.1 117,16.46 102.05,31.41
PETP14_GFXRP14: length 57.5
  TOP w0.1: 93.99,46.76 93.99,46.79 94.04,46.84 94.04,47.15 94.2,47.32 94.2,48.21 93.96,48.45 93.96,48.79 U1.M30
  TOP w0.125: 102.64,32.59 97.1,38.12 97.1,40.15 93.99,43.26 93.99,46.76
  TOP w0.127: 102.64,32.59 121,14.22 121,13.55 TP119.1 121,12.65 121,6.1 120.65,5.75 MPCIE1.B74
PETP15_GFXRP15: length 59.2
  TOP w0.1: 94.72,46.56 94.72,46.59 94.77,46.64 94.77,48.34 94.87,48.44 94.87,48.74 94.78,48.83 94.78,49.16 U1.L29
  TOP w0.125: 94.72,46.56 94.72,44.43 98.35,40.8 98.35,38.8 125,12.15 125,11.55 TP121.1
  TOP w0.127: MPCIE1.B78 124.65,5.75 125,6.1 125,10.65 TP121.1
PFB: length 3.9
  TOP w0.1: Q4101.1 152.66,29.35 C4100.1 R4103.2 152.66,32.92 D4100.2
PRESENCE: length 124.2
  TOP w0.3: MPCIE1.B81 127.55,4.1 127.55,7.7 v3(128.15,8.3)
  L2_INNER w0.2: 44.15,-1.5 44.15,7.84 44.31,8 46.44,8 v3(46.49,7.95) 45.95,7.41 45.95,6.3 46.25,6 54.95,6 55.4,6.45 55.4,8.9 56.14,9.65 58.27,9.65 58.75,9.17 58.75,6.57 59.52,5.8 126.35,5.8 128.1,7.55 128.1,8.25 v3(128.15,8.3) 130.15,8.3 130.15,-1.5
  BOTTOM w0.3: MPCIE1.A1 45.65,7.11 v3(46.49,7.95)
PSEQ_LDO_EN: length 7.7
  TOP w0.5: R845.1 138.65,105.8 138.15,105.3 135.85,105.3 135.35,105.8 132.83,105.8 Q841.1
PSEQ_MVDD_EN: length 1.9
  TOP w0.5: R846.1 136.73,106.21 Q842.1
PSEQ_N1: length 86.6
  TOP w0.1: Q852.1 75.49,108.56 v3(75.35,108.7)
  BOTTOM w0.1: v3(75.35,108.7) 73.64,110.41 25.56,110.41 19.7,104.55 19.7,82.97 C846.1 R857.2 20.23,82.1 19.7,81.56 Q850.3
PSEQ_N2: length 6.1
  BOTTOM w0.1: R851.1 21.25,76.23 Q851.1 21.14,74.56 21.14,73.17 22.23,72.08 R850.2
PSEQ_N3: length 3.3
  BOTTOM w0.1: R852.1 R853.1 22.52,80.95 Q850.1
PSEQ_VDDCUP: length 5.4
  TOP w0.5: C841.1 R841.2 143.31,106.46 142.55,105.7 141.15,105.7 Q840.1
PWM_B: length 27
  TOP w0.1: Q4011.3 148.39,25.44 149.47,26.52 153.59,26.52 154.05,26.97 154.05,28.5 154.55,29 156.15,29 156.86,28.29 Q4100.3 159.64,31.69 160.55,32.6 R4102.2 155.95,32.79 R4111.1 R4103.1
PWM_ENB: length 4.9
  TOP w0.1: R4057.1 143.55,24.61 R4063.1 C4402.1 144.86,24.19 Q4011.1
PWM_R: length 1.7
  TOP w0.1: R4101.2 157.35,30.8 Q4100.1
PWR_ENABLE#: length 14.8
  TOP w0.5: R843.1 149.44,108.5 142.61,108.5 Q840.3 139.91,106.94 139.66,107.19 R845.2 R846.2
PWRGOOD_GPU: length 4.8
  TOP w0.3: v3(92.55,64.3) 92.65,64.2 U1.N10
  BOTTOM w0.3: R59.2 89,63.6 89.38,63.98 90.98,63.98 91.15,63.81 R60.1 91.76,63.81 92.25,64.3 v3(92.55,64.3)
PX_EN: length 2.3
  TOP w0.1: v1(84.5,60.22) 84.93,60.22 U1.AB16
  BOTTOM w0.1: R7.2 84.03,59.75 v1(84.5,60.22)
R2SET: length 2.5
  TOP w0.25: v1(81.29,63.04) 81.38,62.95 81.38,62.47 81.34,62.44 81.34,62.21 U1.AG13
  BOTTOM w0.4: R23.1 80.43,63.54 80.92,63.04 v1(81.29,63.04)
R_DAC2: length 62.9
  TOP w0.155: MR1015.2 22.64,17.99 v3(23.45,18.8) ; v3(7.95,66.9) R2003.1 C2001.1 7.24,68.69 L2001.1
  BOTTOM w0.155: v3(7.95,66.9) 8.28,66.57 8.53,66.57 8.85,66.25 8.85,65 6.55,62.7 6.55,46.21 12.73,40.03 12.73,30.52 13.51,29.74 13.51,26.24 20.44,19.31 21.67,19.31 22.58,18.4 23.05,18.4 v3(23.45,18.8)
RASA#0: length 67.8
  TOP w0.097: 137.37,43.22 137.37,42.86 137.24,42.74 137.21,42.74 137.02,42.56 137.02,42.27 137.21,42.09 137.21,41.94 137,41.73 135.84,41.73 135.72,41.85 135.72,42.1 135.84,42.23 v3(136.39,42.23) 136.39,42.35 136.6,42.57 136.61,42.57 136.85,42.81 136.85,42.82 136.93,42.9 136.93,43.12 136.65,43.4 136.65,43.84 136.23,44.25 135.47,44.25 135.38,44.34 135.38,49.58 134.71,50.25 134.7,50.25 133.44,51.52 129.23,51.52 129.23,51.51 129.04,51.51 128.57,51.98 128.57,51.98 128.31,52.24 126.87,52.24 125.73,52.24 125.65,52.32 125.65,52.45 125.79,52.59 127.63,52.59 127.69,52.65 127.69,52.81 127.62,52.88 125.63,52.88 125.56,52.95 125.56,53.12 125.63,53.19 126.97,53.19 127.09,53.31 127.09,53.46 126.96,53.59 126.59,53.59 126.49,53.69 126.49,53.9 126.39,53.99 126.19,53.99 126.09,53.9 126.09,53.69 125.99,53.59 125.69,53.59 125.56,53.72 125.56,54.6 125.84,54.87 125.84,55.05 125.96,55.17 126.29,55.17 126.52,54.95 126.52,54.7 126.41,54.59 v5(126.29,54.59)
  TOP w0.1: v1(98,55.4) 98,55.05 U1.G22
  BOTTOM w0.097: v3(136.39,42.23) 136.28,42.23 135.29,43.22 134.16,43.22
  BOTTOM w0.1: v1(98,55.4) 98.39,55.4 98.51,55.28 101.94,55.28 102.39,55.73 102.39,55.75 102.59,55.95 103.94,55.95 105.2,54.68 124.81,54.68 125.09,54.41 125.16,54.41 125.16,54.41 125.71,54.41 125.89,54.59 v5(126.29,54.59)
RASA#1: length 64.3
  TOP w0.097: v3(128.68,65.06) 128.88,65.27 129.18,65.27 129.47,65.55 133.78,65.55 133.81,65.58 133.81,65.58 133.84,65.61 133.85,65.61 134.76,66.53 134.76,66.74 135.31,67.28 135.31,70.21 135.71,70.61 135.71,71.32 135.34,71.69 135.34,71.75 134.85,72.24 134.85,72.32 134.84,72.34 134.84,72.57 134.59,72.82 134.59,73.37 134.88,73.67 135.14,73.67 135.26,73.8 135.26,73.81 135.59,74.14 135.78,74.14 135.93,74.28 v3(135.93,74.39) 135.99,74.39 136.12,74.52 136.12,74.75 135.99,74.88 135.38,74.88 135.32,74.82 135.26,74.82 135.19,74.75 135.19,74.27 134.95,74.02 134.93,74.02 134.44,73.53 134.32,73.53 U401.J3 ; v1(127.07,57.16) 126.83,57.4 126.83,58.51 127.01,58.69 127.01,61.74 127.47,62.2 127.5,62.2 127.52,62.22 v5(127.52,62.22)
  TOP w0.1: U1.G17 97.75,58.55 v1(98.1,58.9)
  BOTTOM w0.097: v3(135.93,74.39) 136.56,74.39 137.37,73.59 137.37,73.38
  BOTTOM w0.1: v1(98.1,58.9) 98.1,58.84 98.56,58.38 100.07,58.38 100.23,58.54 102.05,58.54 102.48,58.1 105.74,58.1 106.46,57.38 125.66,57.38 126.06,56.99 126.94,56.99 127.09,57.14 127.09,57.14 v1(127.07,57.16) ; v3(128.68,65.06) 127.47,63.86 127.03,63.86 126.81,63.63 126.81,63.17 126.9,63.08 126.9,62.81 127.02,62.69 127.12,62.69 127.14,62.66 127.94,62.66 128.07,62.54 128.07,62.06 128.07,62.06 128.07,61.88 127.98,61.79 127.41,61.79 127.32,61.88 127.32,62.09 127.45,62.22 v5(127.52,62.22)
RB_DAC2: length 60
  TOP w0.155: MR1027.2 24.37,17.89 23.56,17.89 v3(23.45,18) ; R2027.1 v3(7.94,66)
  BOTTOM w0.155: v3(7.94,66) 8.21,66.27 8.41,66.27 8.55,66.13 8.55,65.12 6.25,62.82 6.25,46.08 12.42,39.91 12.42,30.4 13.21,29.61 13.21,26.11 20.31,19.01 21.54,19.01 22.46,18.1 23.35,18.1 v3(23.45,18)
REST_CTF: length 38.7
  TOP w0.1: R4401.1 76.07,98.92 76.07,101.47 76.71,102.11 76.71,104.83 81.08,109.2 101.74,109.2 R4402.2 104.45,107.9 R4400.1 106,106.35 D4400.3
RSET: length 1.6
  TOP w0.3: U1.AD22 84.12,54.83 84.1,54.83 v1(83.53,55.41)
  BOTTOM w0.3: R12.2 83.99,54.94 v1(83.53,55.41)
SCL: length 21.1
  TOP w0.1: R597.1 R33.1 88.31,84.85 90.38,84.85 93.14,82.09 93.14,77.1 91.62,75.57 91.62,70.07 U1.R1
SCL_R: length 2.9
  TOP w0.1: U4001.10 74.65,93.73 73.96,94.41 73.5,94.41 R4001.2
SDA: length 21.4
  TOP w0.1: R596.1 R34.1 88.36,83.9 91.05,83.9 92.94,82.01 92.94,77.18 91.42,75.66 91.42,70.46 91.03,70.08 91.03,69.67 91.35,69.35 U1.R3
SDA_R: length 2.4
  TOP w0.1: U4001.9 75.15,93.9 R4002.2
SMCLK: length 16.7
  TOP w0.1: MPCIE1.B5 49.65,6.08 51.92,8.35 51.92,15.18 R4.2 52.36,15.61 52.85,16.1 52.85,17.06 Q2.3
SMDAT: length 20
  TOP w0.1: Q1.3 57.95,16.85 57.02,15.93 53.77,15.93 R3.2 53.16,15.61 52.15,14.6 52.15,8.3 50.65,6.8 MPCIE1.B6
SS_SEL0: length 3.7
  BOTTOM w0.1: MR71.2 66.32,65.17 R71.1 66.78,66.83 66.78,67.01 66.79,67.03 66.79,67.69 67.19,68.09 U12.7
SS_SEL1: length 2.6
  BOTTOM w0.1: U12.3 70.59,68.64 71.05,68.64 71.76,69.34 MR70.2 R70.1
SWAPLOCKB: length 5
  TOP w0.1: TP123.1 76.65,62.98 80.5,62.98 80.88,62.6 U1.AH12
TCRIT: length 1.5
  TOP w0.1: R4065.1 74.62,90.49 U4001.1
TESTEN: length 35.5
  TOP w0.1: U1.K7 95.35,66.58 v1(95.77,66.16)
  BOTTOM w0.1: J4004.2 100.25,92.82 100.25,89.2 R436.2 R37.1 100.75,85.89 100.75,82.61 97.45,79.31 97.45,74.33 98.25,73.53 99.27,73.53 99.45,73.34 99.45,68.74 98.12,67.41 98.12,67.24 96.67,65.8 96.13,65.8 v1(95.77,66.16)
TESTEN_LEGACY: length 1.6
  TOP w0.1: U1.AF24 82.55,52.95 v1(82.94,52.56)
  BOTTOM w0.1: R35.1 82.94,53.37 v1(82.94,52.56)
THERMINT: length 1.9
  TOP w0.1: R4080.2 76.15,95.09 U4001.7
TMDP_EN: length 4.9
  TOP w0.1: Q1601.1 17.83,47.51 R844.2 C843.1 20.07,46.09 Q2701.1
TS_FDO: length 192.2
  TOP w0.1: R4081.2 77.36,88.51 77.35,88.5 v3(77.08,88.5) ; v3(143.97,27.46) 144.65,27.46 145.57,26.54 147.35,26.54 147.78,26.97 151.31,26.97 151.56,26.72 153.51,26.72 153.85,27.06 153.85,28.58 154.47,29.2 156.23,29.2 156.94,28.49 157.99,28.49 158.44,28.94 R4101.1 v3(159.15,30.9) ; R4100.2 74.84,87.79 v3(75.02,87.62) 75.51,87.12 76.16,87.12 80.68,82.6 89.95,82.6 90.42,82.13 90.42,70.9 90.11,70.58 90.11,69.71 90.02,69.63 90.02,69.16 90.25,68.94 90.25,68.48 90.44,68.28 91.27,68.28 U1.R5
  BOTTOM w0.1: v3(143.97,27.46) 145.85,29.34 145.85,82.21 131.84,96.22 101.96,96.22 99.87,94.13 79.3,94.13 77.08,91.91 v3(77.08,88.5) 76.19,87.62 v3(75.02,87.62)
UNNAMED_1_RES_I16_A: length 3.1
  TOP w0.1: R63.1 60.25,11.81 R65.2 60.06,13.1 59.25,13.1 58.9,12.75 U4.1
UNNAMED_4_CAP_I24_A: length 3.9
  TOP w0.3: C499.1 R222.1 126,50.23 125.9,50.13 v1(125.9,50.12) ; v1(125.91,51.44) 126.54,51.44 R221.2
  BOTTOM w0.3: v1(125.9,50.12) 125.91,50.14 v1(125.91,51.44)
UNNAMED_4_CAP_I139_A: length 4.8
  TOP w0.3: v5(125.71,63.08) 125.72,63.08 R224.1
  TOP w0.4: R223.2 126.56,65.36 C500.1 126.25,65.37 125.89,65.01 125.89,64.77 125.87,64.75 125.87,64.7 125.83,64.7 125.83,64.7 v3(125.83,64.7)
  BOTTOM w0.3: v5(125.71,63.08) 125.73,63.11 125.73,63.13 125.72,63.14 125.72,64.61 125.87,64.75 125.87,64.7 125.83,64.7 125.83,64.7 v3(125.83,64.7)
UNNAMED_4_DDR364MX1623E22387M_1: length 4.7
  TOP w0.2: 132.05,44.41 132.88,44.41 133.29,44.81 133.37,44.81
  TOP w0.3: R218.1 129.15,44.81 v4(130.51,44.81) 130.63,44.69 131.77,44.69 132.05,44.41
UNNAMED_4_DDR364MX1623E22387M_2: length 4.9
  TOP w0.4: R217.1 142.22,45.13 v4(141.28,45.13) 141.23,45.08 140.93,45.08 140.25,44.4 v3(139.55,44.4)
  BOTTOM w0.2: U201.L8 138.34,44.81 138.74,44.41 139.13,44.41 139.14,44.4 v3(139.55,44.4)
UNNAMED_4_DDR364MX1623E22387M_3: length 5
  TOP w0.2: U401.L8 138.41,71.78 138.8,71.38 139.17,71.38 139.36,71.58 139.41,71.58 139.47,71.64 139.69,71.85
  TOP w0.3: 139.69,71.85 v4(140.91,71.85) 141.57,71.85 R219.1
UNNAMED_4_DDR364MX1623E22387MNG: length 4.8
  BOTTOM w0.2: 133.37,71.78 133.25,71.89 133.01,71.89 132.73,72.17 132.01,72.17 131.88,72.05 131.88,72.03
  BOTTOM w0.3: 131.88,72.03 131.59,71.73 130.65,71.73 v4(130.48,71.56) 130.32,71.73 129.21,71.73 R220.1
UNNAMED_5_CAP_I72_A: length 8.3
  TOP w0.1: Y2.1 68.26,28.19 66.79,29.66 C82.1 66.8,31.61 R31.1 R30.2
UNNAMED_5_CAP_I92_B: length 1.2
  BOTTOM w0.1: C94.2 R296.1
UNNAMED_5_CAP_I102_B: length 1.2
  BOTTOM w0.1: C95.2 R297.1
UNNAMED_5_RES_I15_B: length 62.4
  TOP w0.1: R36.2 70.15,32.85 69.11,33.88 66.32,33.88 60.99,39.22 v3(60.99,40.77)
  BOTTOM w0.1: v3(60.99,40.77) 60.99,59.97 63.27,62.25 63.27,68.17 64.58,69.47 64.82,69.47 65.25,69.05 65.28,69.05 MR75.2 65.07,68.74 64.61,68.74 63.65,67.78 63.65,63.2 64,62.85 64.7,62.85 64.85,63 64.85,63.5 65.38,64.03 67.22,64.03 67.8,64.62 69.03,64.62 69.19,64.78 69.19,65.71 R76.2 70.52,67.04 71.2,67.04 71.56,67.4 R75.2
UNNAMED_6_CAP_I32_A: length 5.4
  TOP w0.1: R1016.2 22.47,19.51 C1002.1 19.04,17.1 L1002.1
UNNAMED_6_CAP_I51_A: length 4.9
  TOP w0.1: L1001.1 20.17,14.7 C1001.1 R1015.2
UNNAMED_6_CAP_I68_A: length 5.9
  TOP w0.1: R1017.2 C1003.1 18.06,19.59 L1003.1
UNNAMED_7_NPN_I43_B: length 28.7
  TOP w0.1: R4410.1 17.64,65.59 Q4402.1 22.11,70.44 21.95,70.6 21.61,70.6 19.61,68.6 16.55,68.6 15.45,69.7 15.45,72.8 16.15,73.5 18.45,73.5 18.75,73.2 19.35,73.2 19.91,73.76 R2527.1 20.08,72.58 Q2513.1
UNNAMED_11_CAP_I2_B: length 3.8
  TOP w0.5: R612.1 72.55,102.29 R609.2 70.74,102.8 R614.2 C612.2
UNNAMED_11_CAP_I4_B: length 1.5
  TOP w0.5: R612.2 C611.2
UNNAMED_11_CAP_I15_B: length 1.7
  TOP w0.4: R613.2 70.15,100.8 71.06,99.89 C613.2
UNNAMED_12_CAP_I15_B: length 4
  TOP w0.4: C712.2 143.47,99.87 R712.1 143.83,100.49 R714.2 142.46,100.98 R709.2
UNNAMED_12_CAP_I22_B: length 1.1
  TOP w0.4: C711.2 R712.2
UNNAMED_12_CAP_I23_B: length 1.4
  TOP w0.4: R713.2 143.33,102.98 143.25,102.9 C713.2
UNNAMED_13_2480063100GUP7701_I1: length 3.4
  BOTTOM w0.5: R856.1 47.73,47.9 U851.5
UNNAMED_14_NPN_I18_E: length 5.9
  BOTTOM w0.1: Q850.2 20.28,78.53 19.74,77.99 Q851.3
UNNAMED_15_MOSN_I38_D: length 3.8
  TOP w0.1: Q4014.3 110.86,106.18 R4056.1
UNNAMED_15_MOSN_I38_G: length 20
  TOP w0.1: R4055.1 109.75,107.81 Q4014.1 109.74,104.06 v3(109.74,101.99) ; Q4013.3 Q4016.3 v3(101.54,101.99)
  BOTTOM w0.1: v3(101.54,101.99) v3(109.74,101.99)
UNNAMED_15_NPN_I34_B: length 3.2
  TOP w0.1: R4060.2 101.92,97.32 101.92,98 101.57,98.35 Q4016.1
UNNAMED_15_NPN_I128_C: length 2.8
  TOP w0.1: Q4401.3 96.41,106.35 R4405.2
UNNAMED_15_PNP_I17_E: length 11.2
  TOP w0.1: R4105.2 155.06,30.1 152.78,27.82 Q4101.2 150.55,27.35 150.54,27.36 Q4102.2
UNNAMED_15_PNP_I27_C: length 35.5
  TOP w0.1: v3(120.15,98.3) 120.45,98.6 120.45,104.2 118.3,106.35 Q4008.3 ; R4045.1 R4050.2 v3(99.47,96.44)
  BOTTOM w0.1: v3(120.15,98.3) 103.94,98.3 103.5,97.87 100.89,97.87 v3(99.47,96.44)
UNNAMED_15_RES_I36_A: length 8.2
  TOP w0.1: D4100.1 155.17,33.4 160.94,33.4 R4112.2 R4113.1
UNNAMED_16_RES_I36_B: length 1.5
  BOTTOM w0.4: TP500.1 84.82,77.28 R595.2
UNNAMED_16_RES_I44_A: length 1.7
  BOTTOM w0.1: SW4002.4 92.62,99.16 NR4000.1
VDIFF: length 8.2
  TOP w0.5: Q4103.1 151.14,23.35 R4106.1 C4102.1 155.07,27.33 Q4101.3
VREFC_U201: length 7.8
  TOP w0.1: R201.2 142.46,47.99 v4(142.9,48.44)
  TOP w0.4: v3(139.95,45) 139.95,45.1 140.65,45.8 140.96,45.8 140.99,45.83 141.57,45.83 141.6,45.8 C413.1 R202.1 R201.2
  BOTTOM w0.2: v3(139.95,45) 139.35,45 139.14,45.21 138.74,45.21 138.34,45.62 138.16,45.62
VREFC_U202: length 6.9
  TOP w0.2: 133.37,45.62 132.97,45.22 132.13,45.22 132.03,45.12 131.58,45.12
  TOP w0.3: 131.58,45.12 131.4,45.3 131.4,45.31 130.67,46.04 v4(130.19,46.04) 129.75,45.6 C438.1 R204.1 R203.2
VREFC_U401: length 6.8
  TOP w0.2: U401.M8 138.41,70.97 138.8,70.58 139.31,70.58 139.35,70.62 139.86,70.62 139.89,70.59
  TOP w0.3: 139.89,70.59 v4(140.84,70.59) 141.06,70.59 141.19,70.47 141.99,70.47 C463.1 R206.1 R205.2
VREFC_U402: length 6.4
  BOTTOM w0.2: 132.82,70.63 132.76,70.58 132.4,70.58 132.4,70.58 131.65,70.58
  BOTTOM w0.25: 133.37,70.97 133.16,70.97 132.82,70.63
  BOTTOM w0.3: R207.2 127.44,70.68 R208.1 C448.1 129.45,70.7 130,70.7 v4(130.46,70.24) 130.81,70.58 131.65,70.58
VREFD_U201: length 5.8
  BOTTOM w0.3: 132.56,42.41 131.76,43.22 130.22,43.22 v4(130.18,43.26) 130.15,43.26 130.15,43.36 129.2,43.36 C486.1 R210.1 R209.2
VREFD_U202: length 7.4
  TOP w0.1: v4(141.44,41.46) 141.45,41.46 141.45,41.49 141.51,41.55 141.91,41.55 R211.2
  TOP w0.4: R211.2 R212.1 C487.1 142.16,43.7 141.25,43.7 140.87,43.31 139.96,43.31 139.06,42.41 U202.H1
VREFD_U401: length 6.1
  TOP w0.3: R214.1 R213.2 C488.1 129.1,74.55 129.78,74.55 130.41,73.92 v4(130.7,73.92) 131.03,73.59 131.84,73.59 132.42,74.17 132.56,74.17
VREFD_U402: length 6.2
  BOTTOM w0.3: U402.H1 139.98,73.16 v4(141.11,73.16)
  BOTTOM w0.4: R216.1 R215.2 C489.1 142.28,73.94 141.51,73.16 v4(141.11,73.16)
VREFG: length 14.4
  TOP w0.3: U1.AC16 84.96,59.6 85.16,59.4 85.16,59.03 v1(85.23,58.97)
  L3_INNER w0.2: v1(85.23,58.97) 85.23,59.41 84.95,59.7 84.95,60.03 84.95,60.03 84.95,60.41 84.95,60.41 84.95,60.5 84.75,60.7 79.56,60.7 v3(78.85,61.41)
  BOTTOM w0.3: C53.2 76.81,62.04 77.3,61.55 78.71,61.55 v3(78.85,61.41)
  BOTTOM w0.5: R21.2 74.64,61.49 75.19,62.04 R22.2 C53.2
WEA#0: length 65.9
  TOP w0.097: v1(129.12,52.33) 129.16,52.38 129.31,52.38 129.35,52.33 129.5,52.33 129.62,52.21 129.62,52.11 129.75,51.98 133.53,51.98 134.87,50.65 134.88,50.65 135.78,49.74 135.78,45.2 135.93,45.05 135.94,45.05 136.12,44.87 v1(136.38,44.87) 136.38,44.99 136.5,45.11 136.66,45.11 136.78,44.98 136.78,44.69 136.6,44.5 136.6,44.46 136.78,44.27 136.78,44.27 136.88,44.17 137.04,44.17 137.23,44.36 137.23,44.46 137,44.69 137,44.84 137.12,44.97 137.28,44.97 137.37,44.88 137.37,44.81
  TOP w0.1: U1.G25 v1(98.15,52.6)
  BOTTOM w0.097: v1(136.38,44.87) 135.64,45.14 134.77,45.14 134.71,45.13 134.34,44.91 U201.L3
  BOTTOM w0.1: v1(129.12,52.33) 129.2,52.25 129.2,52.08 129.03,51.83 128.96,51.76 128.83,51.76 128.73,51.85 128.73,52.02 128.61,52.14 128.59,52.14 128.59,52.14 128.04,52.14 127.92,52.02 127.92,51.89 127.86,51.82 127.68,51.82 127.62,51.89 127.62,52.05 127.54,52.14 127.24,52.14 127.16,52.05 127.16,51.97 127.03,51.84 126.8,51.84 126.66,51.99 126.66,52.17 126.59,52.23 124.54,52.23 124.4,52.09 124.4,51.97 124.35,51.91 124.35,51.86 124.29,51.8 124.13,51.8 124.02,51.92 124.02,52.01 123.9,52.13 114.42,52.13 114.42,52.13 114.02,52.13 113.97,52.17 113.97,52.44 113.9,52.51 113.71,52.51 113.67,52.47 113.67,52.17 113.63,52.13 113.45,52.13 113.32,52.26 113.32,52.39 113.24,52.48 113.11,52.48 113.02,52.38 113.02,52.21 112.93,52.12 112.81,52.12 112.72,52.21 112.72,52.39 112.64,52.48 112.51,52.48 112.42,52.38 112.42,52.21 112.33,52.12 112.21,52.12 112.12,52.21 112.12,52.39 112.04,52.48 111.91,52.48 111.82,52.38 111.82,52.21 111.73,52.12 111.61,52.12 111.52,52.21 111.52,52.39 111.43,52.48 111.31,52.48 111.22,52.38 111.22,52.21 111.13,52.12 111,52.12 110.92,52.21 110.92,52.39 110.83,52.48 110.71,52.48 110.62,52.38 110.62,52.21 110.53,52.12 110.4,52.12 110.32,52.21 110.32,52.39 110.23,52.48 110.11,52.48 110.01,52.38 110.01,52.21 109.93,52.12 109.8,52.12 109.71,52.21 109.71,52.39 109.63,52.48 109.51,52.48 109.41,52.38 109.41,52.21 109.33,52.12 109.2,52.12 109.11,52.21 109.11,52.39 109.03,52.48 108.91,52.48 108.81,52.38 108.81,52.21 108.72,52.12 108.6,52.12 108.51,52.21 108.51,52.39 108.43,52.48 108.3,52.48 108.21,52.38 108.21,52.21 108.12,52.12 108,52.12 107.91,52.21 107.91,52.39 107.83,52.48 107.7,52.48 107.61,52.38 107.61,52.21 107.52,52.12 107.4,52.12 107.31,52.21 107.31,52.39 107.23,52.48 107.1,52.48 107.01,52.38 107.01,52.21 106.92,52.12 106.8,52.12 106.71,52.21 106.71,52.43 106.63,52.51 106.49,52.51 106.41,52.43 106.41,52.21 106.32,52.12 106.19,52.12 106.11,52.21 106.11,52.43 106.03,52.51 105.89,52.51 105.81,52.43 105.81,52.21 105.72,52.12 105.59,52.12 105.51,52.21 105.51,52.43 105.43,52.51 105.29,52.51 105.21,52.43 105.21,52.21 105.12,52.12 104.99,52.12 104.9,52.21 104.9,52.43 104.82,52.51 104.68,52.51 104.6,52.43 104.6,52.21 104.52,52.12 104.39,52.12 104.3,52.21 104.3,52.43 104.22,52.51 104.08,52.51 104,52.43 104,52.21 103.91,52.12 103.79,52.12 103.7,52.21 103.7,52.43 103.62,52.51 103.48,52.51 103.4,52.43 103.4,52.21 103.31,52.12 102.61,52.12 102.5,52.02 102.5,51.74 102.46,51.7 102.25,51.7 102.2,51.74 102.2,51.91 102.12,51.99 102.11,51.99 101.83,51.99 101.75,51.91 101.75,51.9 101.65,51.8 101.52,51.8 101.46,51.86 101.46,51.94 101.4,51.99 101.16,51.99 101.1,51.94 101.1,51.44 101.02,51.35 100.89,51.35 100.8,51.44 100.8,51.9 100.72,51.98 100.59,51.98 100.5,51.9 100.5,51.44 100.42,51.35 100.29,51.35 100.2,51.44 100.2,51.89 100.12,51.98 99.99,51.98 99.9,51.89 99.9,51.44 99.82,51.35 99.69,51.35 99.6,51.44 99.6,51.95 99.52,52.04 99.49,52.04 99.46,52.07 99.33,52.14 98.86,52.38 98.8,52.38 98.57,52.6 v1(98.15,52.6)
WEA#1: length 67.2
  TOP w0.097: v1(128.52,66.56) 128.31,66.56 128.18,66.68 128.18,67.14 128.31,67.27 129.3,67.27 129.43,67.14 129.43,66.85 129.35,66.77 129.06,66.77 128.97,66.68 128.97,66.48 129.09,66.36 129.3,66.36 129.43,66.23 129.43,66.14 129.55,66.02 131.23,66.02 131.23,66.02 131.25,66.02 131.26,66.01 131.78,66.01 131.78,66.02 133.68,66.02 134.36,66.7 134.36,66.91 134.91,67.45 134.91,70.44 135.11,70.64 v1(135.11,70.94) 135.06,70.94 134.53,70.41 134.44,70.41 134.31,70.53 134.31,70.64 134.51,70.83 134.51,71.12 134.31,71.32 134.02,71.32 133.8,71.09 133.75,71.09 133.53,71.31 133.53,71.45 133.71,71.63 133.71,71.7 133.89,71.88 134.06,71.88 U401.L3
  TOP w0.1: U1.H10 96.65,64.2 96.55,64.3 96.55,64.5 96.65,64.6 v1(98.15,64.6)
  BOTTOM w0.097: v1(135.11,70.94) 135.11,70.97 135.91,71.77 137.35,71.77 137.37,71.78
  BOTTOM w0.1: v1(98.15,64.6) 98.1,64.65 98.1,64.84 98.2,64.94 98.37,64.94 98.43,65 98.78,65 98.97,65.19 98.97,65.25 99.09,65.38 99.33,65.38 99.34,65.38 99.36,65.38 99.41,65.33 99.41,65.11 99.5,65.02 99.63,65.02 99.72,65.11 99.72,65.78 99.82,65.89 99.98,65.89 100.08,65.78 100.08,65.31 100.17,65.22 100.3,65.22 100.38,65.31 100.38,65.82 100.47,65.91 100.59,65.91 100.68,65.82 100.68,65.31 100.77,65.22 100.89,65.22 100.98,65.31 100.98,65.67 101.11,65.8 101.3,65.8 101.3,65.76 101.45,65.6 101.45,65.26 101.53,65.18 101.73,65.18 101.81,65.26 101.81,65.49 101.85,65.53 101.86,65.53 101.95,65.61 102.13,65.61 102.26,65.49 102.26,65.28 102.34,65.19 102.47,65.19 102.56,65.28 102.56,65.58 102.61,65.63 102.8,65.63 102.86,65.58 102.86,65.28 102.94,65.19 103.07,65.19 103.16,65.28 103.16,65.45 103.24,65.53 103.3,65.53 103.45,65.38 103.45,64.81 v4(103.73,64.54) 104.05,64.22 112.3,64.22 113.87,62.66 120.19,62.66 120.41,62.44 120.41,62.28 120.59,62.1 120.59,62.09 120.82,61.85 125.53,61.85 125.65,61.98 125.65,62.58 125.75,62.68 125.87,62.68 125.89,62.7 126.16,62.7 126.16,63.2 126.04,63.32 126.04,63.32 126.03,63.33 126.03,64.19 126.28,64.44 126.28,64.86 126.01,65.12 126.01,65.27 126.14,65.39 126.23,65.39 126.27,65.35 126.42,65.35 126.46,65.39 126.68,65.39 126.77,65.48 126.77,65.7 126.95,65.88 127.06,65.88 127.18,65.75 127.18,65.52 127.31,65.39 127.58,65.39 127.71,65.52 127.71,65.62 127.96,65.87 127.96,66.23 127.59,66.59 127.59,66.71 127.6,66.72 127.6,66.86 127.72,66.98 127.9,66.98 128.05,66.83 128.25,66.83 v1(128.52,66.56)
XIN_OSC: length 6.1
  BOTTOM w0.1: Y3.3 70.47,71.59 v4(71.7,71.59) 72.53,71.59 72.7,71.42 C92.1 72.34,70.96 71.53,70.96 71.17,70.61 71.17,69.86 70.91,69.59 U12.1
XO_IN: length 34.9
  TOP w0.1: v1(84.29,56.62) 84.55,56.37 84.55,55.87 84.95,55.46 U1.AC22
  L3_INNER w0.1: v1(84.29,56.62) 83.61,57.3 81.2,57.3 80.1,56.2 74.06,56.2 68.3,61.95 67.46,61.95 64.61,64.8 v3(62.85,64.8)
  BOTTOM w0.1: TR75.2 65.17,69.99 64.06,69.99 62.95,68.88 62.95,64.9 v3(62.85,64.8)
XO_IN2: length 34.6
  TOP w0.1: U1.AB22 85.31,54.6 85.13,54.43 84.72,54.43 84.56,54.59 84.56,54.94 83.71,55.79 83.71,56.27 83.48,56.5 v1(83.48,56.62)
  L3_INNER w0.1: v3(65.35,63.3) 65.83,63.3 67.38,61.75 68.22,61.75 73.97,56 80.18,56 81.28,57.1 83,57.1 v1(83.48,56.62)
  BOTTOM w0.1: v3(65.35,63.3) 65.54,63.49 67.01,63.49 67.94,64.42 69.68,64.42 72.55,67.3 R74.2
XOUT_OSC: length 5.2
  BOTTOM w0.1: U12.10 67.88,69.59 68,69.72 68,70.16 67.78,70.39 67.31,70.39 66.5,71.19 C93.1 67.02,71.85 67.02,71.94 Y3.1
XTALIN: length 23.7
  TOP w0.1: R30.1 69.16,32.59 R36.1 70.75,32.21 70.75,33.6 72.25,35.1 72.25,40.16 73.98,41.9 74,41.9 77.61,45.51 77.61,48.29 78.17,48.85 78.26,48.85 79.21,49.8 U1.AM28
XTALOUT: length 35.8
  TOP w0.1: v3(68.05,33.3) R31.2 65.99,32.59 65.03,31.62 65.03,28.98 64.24,28.19 Y2.2 ; U1.AK28 79.75,49.4 79.09,49.4 78.34,48.65 78.25,48.65 77.81,48.21 77.81,45.43 74.08,41.7 74.08,41.7 72.45,40.07 72.45,34.5 v3(71.35,33.4) 71.25,33.3 C83.1
  BOTTOM w0.1: v3(71.35,33.4) 70.55,32.6 69.45,32.6 68.75,33.3 v3(68.05,33.3)
N857905: length 7.6
  TOP w0.1: R1805.2 32.11,82.54 Q1803.1 29,80.26 Q1804.3
N7393636:
  vias: v2(36.63,24.05) v2(36.63,22.94)

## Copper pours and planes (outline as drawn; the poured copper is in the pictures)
+1.8V on BOTTOM: 72.28,64.34 72.61,64.34 72.93,64.02 72.93,62.99 73.31,62.62 73.31,61.98 73.87,61.41 73.88,61.41 73.88,59.73 73.87,59.72 73.91,59.69 73.91,58.36 72.5,56.95 71.9,56.95 71.55,56.6 71.55,52.07 72.21,51.41 73.08,51.41 73.36,51.13 77.95,51.13 78.05,51.04 78.05,50.19 78.22,50.01 79.16,50.01 79.25,49.92 79.25,48.64 79,48.4 77.78,48.4 75.76,46.38 70.26,46.38 69.9,46.02 69.9,44.05 65.05,39.2 65.05,38.7 62.55,36.2 56.15,36.2 55.75,36.6 55.75,38.2 55.9,38.35 60.8,38.35 62.15,39.7 62.15,52.49 66.05,56.39 66.05,57.2 67.25,58.4 69.42,58.4 71.86,60.84 71.86,63.93
+1.8V_LDOOUT on BOTTOM: 54.45,38.1 54.45,36.3 54.25,36.1 54.25,34.7 54.05,34.5 53.55,34.5 53.25,34.2 52.65,34.2 52.15,33.7 52.15,31.7 52.05,31.6 51.55,31.6 51.25,31.9 51.25,33.4 50.65,34 49.65,34 49.5,34.15 49.5,38.35 49.85,38.7 53.85,38.7
+1V on BOTTOM: 67.94,62.31 68.82,63.2 68.94,63.2 68.97,63.17 68.97,63.2 70.05,63.2 70.75,63.9 70.75,64.04 70.44,64.36 70.22,64.36 69.73,63.86 68.09,63.86 65.59,61.36 65.59,59.76 66.47,58.88 67.64,58.88 68.02,58.88 68.35,59.21 68.35,60.5 67.94,60.91
+1V on BOTTOM: 57.35,48.1 57.15,47.9 54.55,47.9 54.35,48.1 54.35,62.5 54.4,62.55 54.4,64.65 55.25,65.5 56.55,65.5 57.35,64.7
+1V on BOTTOM: 72.06,56.74 77.09,56.74 77.57,56.26 77.57,54.43 77.42,54.28 76.99,54.28 76.83,54.43 76.83,55.04 76.4,55.47 74.7,55.47 74.14,54.91 72.14,54.91 71.81,55.24 71.81,56.49
+1V on L3_INNER: 60.85,62.4 66.25,62.4 67.35,61.3 68.05,61.3 73.45,55.9 73.45,55 73.05,54.6 70.85,54.6 65.55,59.9 59.15,59.9 54.75,64.3 54.75,65.51 55.24,66 57.25,66
